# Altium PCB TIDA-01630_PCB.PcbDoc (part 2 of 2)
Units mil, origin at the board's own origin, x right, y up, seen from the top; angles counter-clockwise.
Board outline 3155 x 2050 mil, 4 copper layers (Top Layer, Signal Layer 1, Signal Layer 2, Bottom Layer), stack 49.055 mil thick; 119 components, 66 nets, 330 pads, 436 vias.
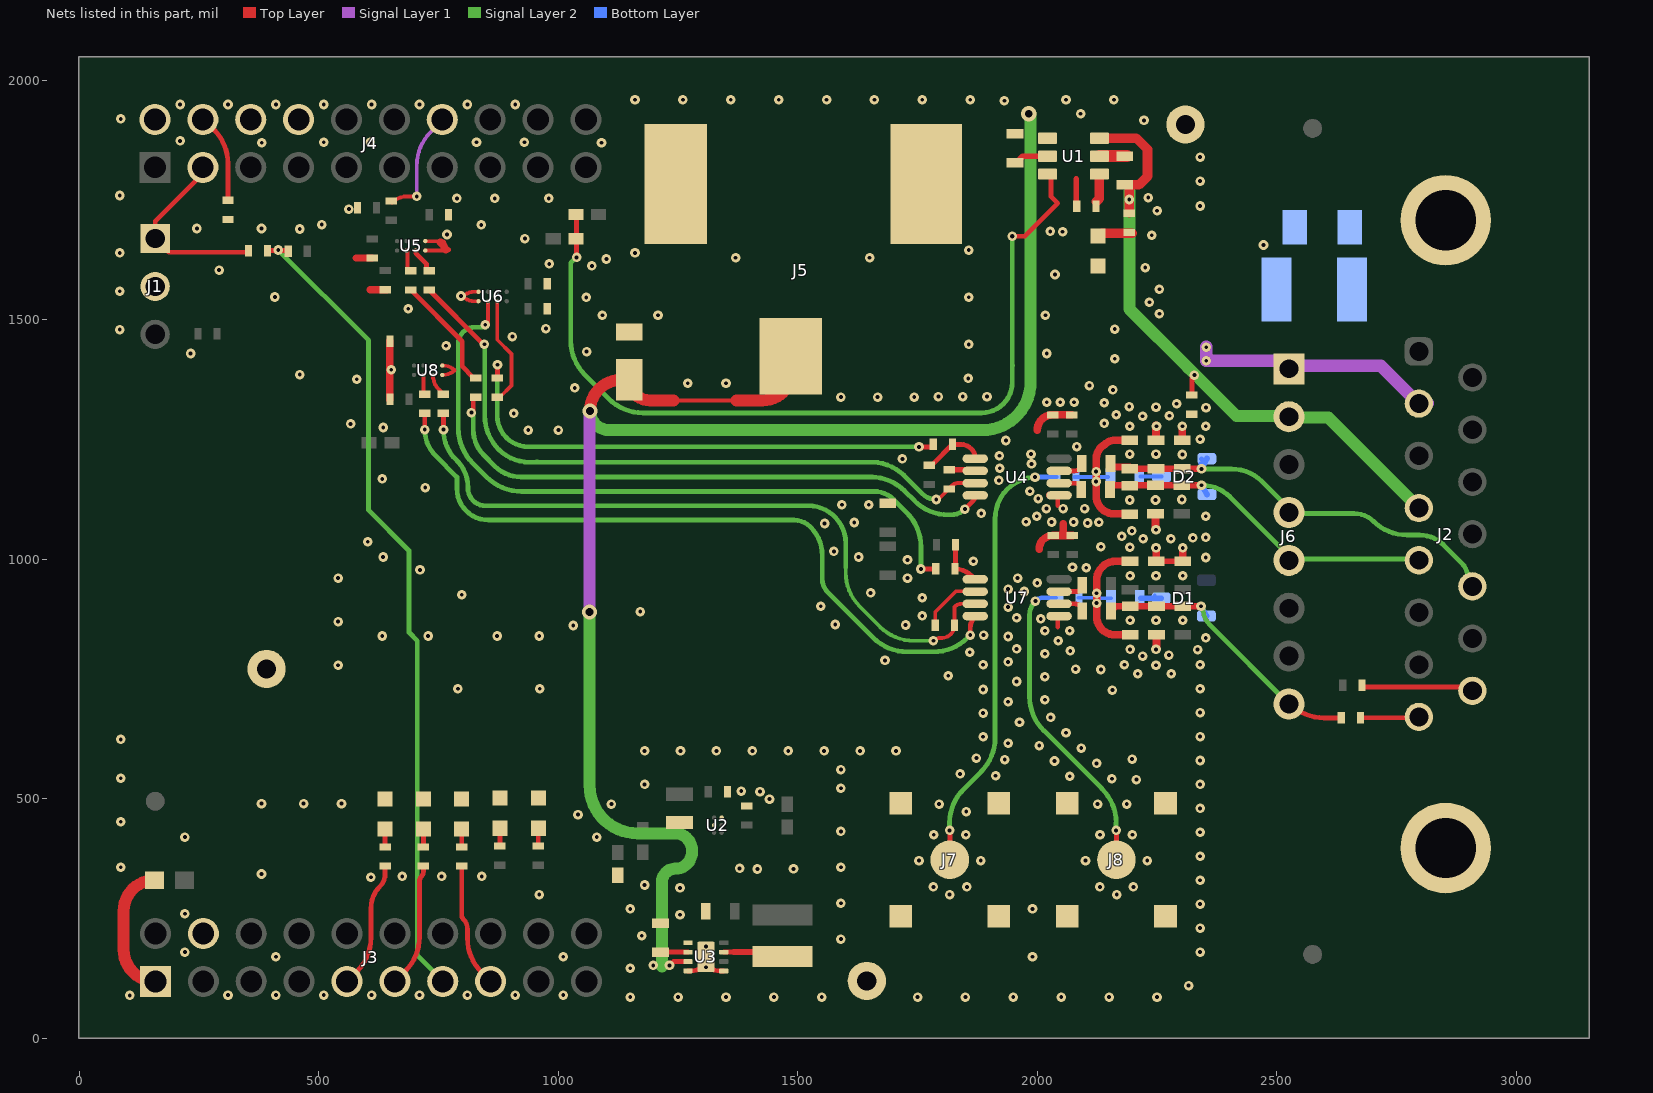
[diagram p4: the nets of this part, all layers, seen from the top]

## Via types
v1: diameter 20, hole 8, Top Layer to Bottom Layer, tented both sides, 371 vias
v2: diameter 20, hole 8, Top Layer to Bottom Layer, 51 vias
v3: diameter 32, hole 16, Top Layer to Bottom Layer, 9 vias
v4: diameter 20, hole 10, Top Layer to Bottom Layer, 3 vias
v5: diameter 19.68, hole 7.87, Top Layer to Bottom Layer, 2 vias

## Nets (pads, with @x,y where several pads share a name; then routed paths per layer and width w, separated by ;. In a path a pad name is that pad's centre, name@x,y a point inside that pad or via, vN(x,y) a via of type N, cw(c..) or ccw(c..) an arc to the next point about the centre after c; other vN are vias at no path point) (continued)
CLK_P: C19.2 D1.2 J6.8 R5.1 R38.1 R39.2 R42.1 | length 600.7
  Top Layer w10: R38.1@2304,902 R38.1@2304,902.33 ; J6.8@2528.09,698.34 ccw(c2598.8,769.05) 2598.8,669.05 R5.1@2634.79,669.05
  Top Layer w14: R39.2@2154,892 2164.33,902.33 R42.1@2194,902.33 C19.2@2249,902.33 R38.1@2304,902.33 ; R38.1@2304,902 v2@2336,902
  Signal Layer 2 w10: v2(2342,902) v2@2345.92,902 ; v2@2345.97,898.03 ccw(c2395.2,898.03) 2360.39,863.23 J6.8@2525.63,697.98
  Bottom Layer w12: v2(2342,902) D1.2@2353.24,881.6
DATA_N: C15.1 D2.1 J2.13 J6.4 R29.1 R31.2 R32.2 | length 911.9
  Top Layer w14: R31.2@2153,1200 2160,1193 R29.1@2193,1193 ; R29.1@2193,1189 C15.1@2248,1189 R32.2@2303,1189 ; R32.2@2307,1189 v2(2343,1189)
  Signal Layer 2 w10: v2(2343,1189) 2405.58,1189 cw(c2405.58,1098.66) 2469.46,1162.54 2518.7,1113.3 ccw(c2540.37,1134.96) J6.4@2540.37,1104.32 ; J6.4@2519.38,1095.95 2661.64,1095.95 cw(c2661.64,1037.76) 2702.78,1078.91 ; J6.4@2528.01,1096.52 J6.4@2529.45,1097.97 ; 2701.43,1080.07 ccw(c2772.15,1150.79) 2772.15,1050.79 2798.43,1050.79 cw(c2798.43,979.84) 2848.6,1030.01 2886.64,991.96 cw(c2856.98,962.3) J2.13@2898.93,962.3 ; J2.13@2901.19,945.89 J2.13@2901.19,969.31
  Bottom Layer w10: D2.1@2343,1209.83 2342.83,1210 D2.1@2343,1210
  Bottom Layer w12: v2(2343,1189) D2.1@2343,1199.51 ; v2@2343.16,1189.5 2347.25,1197.28 D2.1@2354.24,1210.4 D2.1@2354.41,1210.9
DATA_P: C12.2 D2.2 J2.5 J6.5 R22.1 R23.2 R28.2 | length 744.1
  Top Layer w14: R23.2@2152,1149 2158,1155 2193,1155 2215.5,1155 C12.2@2247,1155 R22.1@2302,1155 ; R22.1@2305,1155 v2(2343,1155)
  Signal Layer 2 w10: v2(2343,1155) cw(c2343,1070.46) 2402.78,1130.24 J6.5@2530.33,1002.68 ; J6.5@2525.25,999.52 J6.5@2533.31,999.52 ; J6.5@2530.55,996.76 J6.5@2533.31,999.52 ; J6.5@2535.33,1001.54 J6.5@2534.63,1000.84 ; J2.5@2799.39,1000.84 J6.5@2534.63,1000.84 ; J6.5@2533.31,999.52 J6.5@2534.63,1000.84
  Bottom Layer w10: v2@2341,1151.17 cw(c2341.83,1151.17) 2341.83,1152 2343,1153.17 v2(2343,1155)
  Bottom Layer w12: v2(2343,1155) D2.2@2354.24,1135.6
ENCODERCABLESHIELD: C1.1 J2.16 J2.17 R1.2
GND: C1.2 C2.2 C3.2 C4.1 C5.2 C6.2 C7.2 C8.2 C9.2 C10.2 C11.2 C12.1 C13.1 C14.1 C15.2 C16.2 C17.2 C18.2 C19.1 C20.1 C21.1 C22.2 C23.1 C24.1 C25.2 D1.3 D2.3 D3.1 D4.1 D5.1 D6.2 D7.1 D8.1 D9.1 J1.2 J2.2 J3.4 J4.2 J5.2 J5.3 J6.1 J7.2 J7.3 J7.4 J7.5 J8.2 J8.3 J8.4 J8.5 R1.1 R3.2 R21.1 R32.1 R34.2 R37.1 R46.1 TP1.1 TP2.1 TP3.1 U1.2 U2.A2 U3.1 U3.4 U3.5 U3.9@1308,170 U4.5 U5.D1 U5.D2 U6.D1 U6.D2 U7.5 U8.D1 U8.D2 | length 1763.6
  Top Layer w8: U5.D1@721.82,1644.8 766.73,1644.8 ccw(c766.73,1652.52) 772.19,1647.06 ; U5.D2@721.82,1664.48 756.84,1664.48 cw(c756.84,1658.19) 761.29,1662.64 ; U8.D1@757.53,1385.16 759.24,1385.16 ccw(c759.24,1418.76) 770,1386.93 ccw(c759.24,1418.76) 783,1395 ccw(c759.24,1371.24) 759.24,1404.84 U8.D2@757.53,1404.84 ; U6.D2@833.01,1539.21 824.3,1539.21 cw(c824.3,1572.81) 800.54,1549.05 cw(c824.3,1525.29) 824.3,1558.89 U6.D1@833.01,1558.89
  Top Layer w10: U3.4@1270.6,140.47 1275.34,140.47 ccw(c1275.34,186.66) U3.9@1307,153.03 ; U3.9@1306,154 ccw(c1338.66,186.66) U3.9@1307,153.03 ; U3.5@1345.4,140.47 1338.66,140.47 cw(c1338.66,186.66) U3.9@1307,153.03 ; 2043,859 U7.5@2043,879 ; 2043,1112 U4.5@2043,1133
  Top Layer w12: C2.2@1955.46,1827.74 1969.77,1842.05 U1.2@2021.59,1842.05 ; C4.1@2081.49,1747.35 2081.49,1794.13 ; C22.2@2248.73,996.16 R46.1@2303.73,996.16 R46.1@2311.77,996.16
  Top Layer w15: 577.31,1629.31 C14.1@611.37,1629.31
  Top Layer w16: 607.44,1563.11 C13.1@641.28,1563.11 ; C23.1@648,1334 C24.1@648,1456 ; 753.86,1662.64 cw(c715.24,1624.01) 764.76,1647.06 ; 2000,1269.76 cw(c2032,1269.76) C11.2@2032,1301.76 C10.2@2072,1302 ; 2004,1021 cw(c2033,1021) C17.2@2033,1050 C18.2@2073,1050 C18.2@2074,1050 ; U4.5@2026.39,1133.61 U4.5@2045.6,1133.61 ; U7.5@2028.38,881.62 U7.5@2045.6,881.62 ; 2054,1050 2054,1074 ; C12.1@2247,1092 2247,1065 ccw(c2248,1065) 2248,1064 v1(2248,1062) ; v1(2248,812) ccw(c2248,813) 2249,813 C19.1@2249,842.33 ; v1(2248,1024) cw(c2248,1023.27) 2248.73,1023.27 C22.2@2248.73,996.16 ; C15.2@2248,1249 v1@2248,1280 ; R32.1@2303,1249 v1(2303,1278) ; v1@2303,1279 v1(2303,1278) ; R46.1@2303.73,996.16 2303.73,1024 v1(2304,1024) ; v1@2304,1277 ccw(c2303,1277) v1(2303,1278)
  Signal Layer 1 w26: v1@2353,1444 v1(2353,1443) v1(2353,1415) J6.1@2506.67,1415 ; J6.1@2520.71,1390.38 J6.1@2535.16,1404.84 ; J6.1@2527.1,1404.84 J6.1@2535.16,1404.84 ; J6.1@2537.18,1406.85 J6.1@2535.16,1404.84 ; J2.2@2815.37,1325.95 2795.78,1325.95 2716.89,1404.84 J6.1@2535.16,1404.84
  Bottom Layer w8: C16.2@2215.13,1173 D2.3@2259.76,1173
  Bottom Layer w12: C25.2@2216.27,919 D1.3@2258.76,919
  other v1: 1150,86 1250,86 1350,86 1450,86 1550,86 1750,86 1850,86 1950,86 2050,86 2150,86 2250,86 104.73,89.5 310,90 410,90 510,90 610,90 710,90 810,90 910,90 1010,90 2316,110 1150,146 410,170 1010,170 1990,170 220,180 2340,180 1590,207 1174,214 2340,230 1254,258 220,260 1150,270 1990,270 2340,280 1590,282 960,300 1816.99,300.01 2165.99,300.01 1254,314 1783,316 1853,316 2130.76,316 2200.76,316 1180,320 2340,330 608.3,336.37 674,338 756,338 840,338 380,343 1415.45,353.43 1491.04,353.73 1378.52,354.66 86,357 1590,357 1753,371 1882,371 2100.76,371 2229.76,371 2340,380 220,420 1080,420 1784,425 1851,425 2131,425 2198.76,425 2340,430 1590,432 86,452 1041,467 1851.82,473.36 2340,480 1110.55,488.96 1795,489 2125.99,489.01 2187,489 380,490 468,490 547,490 1440.81,499.29 1421,515 1382,516 1590,522 1180,530 2340,530 2207,540 2155.99,542.01 86,543 2068,547 1913,548 1839,552 1590,561 2124,574 2036,579 2340,580 1932,582 2198,583 1873,585 1180,600 1255,600 1330,600 1405,600 1480,600 1555,600 1630,600 1705,600 2092,606 2004,611 1939,616.17 86,624 1887,629.75 2340,630 2060,638 1963,660 2028.01,669.99 1887,679 2340,680 1939,702.58 2016,707 2157,727 1887,728.25 790,730 961,730 2340,730 1957,745 2016,755 1814,757 2210,761 2280,761 2133,770 2080,771 540,779 2248,779 1887,780 2182,780 2340,780 1939,786 1682,789 2220,798 2275,800 2016,803 1859,806 2069,809 2194,812 2334.81,811.52 1957,813 2044,830 2352,836 1939,839 632,840 728,840 872,840 960,840 1888,842 2016,851 2068,851 1031,862 1725,863 1578,864 540,870 2194,873 2248,873 2304,873 2007.46,875.61 1957,878 1760,882 1171,891 1939,900.32 1548,902 1760,920 798,926 1652,930 1973,933 1939,938 2000,951 540,961 1729,961 1959,961 2194,966 2248,966 2304,966 711,978 2102.32,982.46 2073.56,983.75 1866.57,995.98 1729,999 2352,1004 634,1005 1627,1005 1575.38,1016.57 2193.42,1025.29 2132.9,1026.55 602,1037 2221,1043 2279,1043 2325,1045 2352,1046 2176.46,1048.07 2197.65,1059.37 1556.01,1074.91 2105.18,1076.01 1618,1077 2128.64,1077.45 1976.59,1078.44 2030,1078 2076,1078 1999,1090 2352,1090 1883,1096 2019,1106 2054,1106 2099,1106 1592,1114 1648,1114 2193,1124 2247,1124 2302,1125 2002,1127 1984.75,1142.41 722,1150 1920,1165 632,1168 1921.77,1190.34 1987.96,1199.39 1718.33,1209.92 1920.92,1216.38 2303,1219 1987,1220 2193,1220 2248,1220 2082.47,1235.64 1934.58,1248.25 2340,1251 937,1270 1000,1270 634.13,1275.45 2193,1278 2249,1278 2352,1278 566,1283 2140,1284 2220,1299 2276,1300 2165,1302 906.61,1304.82 2352.47,1316.98 2248,1318 2192,1319 2291,1325 2140,1327 2020,1328 2048,1328 2077,1328 1590,1339 1666.5,1339 1743,1339 1793.67,1340 1844.33,1340 1895,1340 2158,1354 1034,1358 2109,1363 1270,1368 1350,1368 578.83,1376.18 1856,1378 460,1386 651,1396 2162,1419 232,1430 2020,1430 1059,1434 765.48,1446.19 1857,1449 903.84,1465.32 84,1480 2162,1481 974,1482 1092,1510 1208,1510 2017,1510 2255,1513 686.3,1523.34 2234.12,1537.01 1058,1547 408,1548 1857,1547.5 796.54,1550.05 84,1560 2255,1564 2037,1595 291.44,1604.07 2225.57,1609.26 1069.89,1612.92 980.9,1617.08 1100.26,1627.34 1370,1630 1650,1630 84,1640 1160,1640 1857,1646 2472.43,1656.49 930,1670 2239,1677 767.38,1678.47 2053,1684.29 2027,1685 460,1690 245,1691 380,1691 838.7,1698.42 505.62,1699.11 2250.29,1728.25 562.43,1731.48 2340,1738 788,1754 867,1754 980,1754 2231.71,1755.58 84,1760 2340,1790 2340,1840 380.4,1870.08 1090,1870 510,1871 607.1,1870.74 829,1871 929,1871 210,1874 2222.94,1916.76 86,1920 2090.6,1930.69 210,1950 310,1950 410,1950 510,1950 610,1950 710,1950 810,1950 910,1950 1931.42,1957.84 1160,1960 1260,1960 1360,1960 1460,1960 1560,1960 1660,1960 1760,1960 1860,1960 2060,1960 2160,1960
  other v5: 1308,148.35 1308,191.65
GPIO52: J3.15 R9.2 | length 259.9
  Top Layer w10: R9.2@798,359.57 798,257.66 ccw(c811.66,257.66) 802,248 cw(c782.69,228.69) 810,228.69 810,208.53 ccw(c910,208.53) 839.29,137.82 J3.15@858.49,118.62
GPIO94: J3.11 R10.2 | length 260.1
  Top Layer w10: J3.11@658.49,118.62 680.71,140.84 ccw(c610,211.55) 710,211.55 710,328.34 cw(c723.66,328.34) 714,338 ccw(c704.34,347.66) 718,347.66 R10.2@718,359.57
GPIO97: J3.9 R11.2 | length 265.2
  Top Layer w10: J3.9@558.49,118.62 579.21,139.34 ccw(c508.5,210.05) 608.5,210.05 608.5,270.93 cw(c675.07,270.93) 628,318 ccw(c603.86,342.14) 638,342.14 R11.2@638,359.57
GPIO130: J4.8
GPIO131: J4.6
NetC4_2: C4.2 U1.4 | length 59.8
  Top Layer w20: C4.2@2123.77,1747.35 2129.86,1753.44 U1.4@2129.86,1804.65
NetC16_1: C16.1 R28.1 R29.2 R33.2 | length 362.3
  Top Layer w16: v2@2123,1183 v2(2123,1162.73) 2123,1132.95 ccw(c2160.95,1132.95) 2160.95,1095 R28.1@2193,1095 ; v2(2123,1183.27) 2123,1209.84 ; 2123.13,1209.84 cw(c2157.45,1209.84) 2138.41,1238.4 ; 2140.94,1239.93 ccw(c2157.45,1209.84) 2138.45,1238.43 2141.41,1240.4 ; 2141,1240 cw(c2162.73,1218.27) 2141.41,1240.4 ; R29.2@2193,1249 2162.73,1249 ccw(c2162.73,1218.27) 2150.5,1246.46 ; 2141.41,1240.4 cw(c2162.73,1218.27) 2150.5,1246.46 ; 2141.41,1240.4 2150.5,1246.46
  Bottom Layer w8: R33.2@2078.12,1172 v2@2121,1172 ; v2@2123,1172 C16.1@2148,1172
  Bottom Layer w16: v2(2123,1162.73) 2123,1172 v2(2123,1183.27)
NetC25_1: C25.1 R42.2 R43.1 R47.2 | length 347.6
  Top Layer w16: R43.1@2193.73,996.16 2164.01,996.16 ccw(c2164.01,956.15) 2124,956.15 2124,927.32 2124,881.2 ccw(c2162.87,881.2) 2162.87,842.33 R42.2@2194,842.33
  Bottom Layer w8: R47.2@2085.62,920 v2@2123,920 ; 2124,919 C25.1@2154,919
  Bottom Layer w16: v2(2124,908.73) 2124,919 v2(2124,929.27)
NetD3_2: D3.2 R9.1 | length 37.3
  Top Layer w10: R9.1@798,399.57 D3.2@798,436.87
NetD4_2: D4.2 R10.1 | length 37.3
  Top Layer w10: R10.1@718,399.57 D4.2@718,436.87
NetD5_2: D5.2 R11.1 | length 37.3
  Top Layer w10: R11.1@638,399.57 D5.2@638,436.87
NetD7_2: D7.2 R15.2 | length 64.5
  Top Layer w20: D7.2@2134.27,1681.46 R15.2@2198.8,1681.46
NetD8_2: D8.2 R17.1 | length 37.3
  Top Layer w10: R17.1@878,401.2 D8.2@878,438.5
NetD9_2: D9.2 R20.1 | length 37.3
  Top Layer w10: R20.1@958,401.2 D9.2@958,438.5
NetJ1_1: J1.1 J4.3 R8.2 | length 397.3
  Top Layer w10: J4.3@261.01,1817.45 261.01,1809.64 158,1706.63 J1.1@158,1670 186.57,1641.43 R8.2@353.34,1641.43
NetJ2_8: J2.8 R5.2 | length 147
  Top Layer w10: R5.2@2674.13,669.48 J2.8@2821.14,669.48
NetJ2_15: J2.15 R4.1 | length 249
  Top Layer w10: R4.1@2680.06,733.49 J2.15@2929.1,733.49
NetJ3_1: J3.1 R2.2 | length 286.2
  Top Layer w25: R2.2@156.5,330 ccw(c156.5,265.5) 92,265.5 92,185.11 ccw(c158.49,185.11) J3.1@158.49,118.62
NetJ3_13: J3.13 R7.2 R8.1 | length 1710.4
  Top Layer w10: R8.1@395.26,1645.47 395.73,1645 R7.2@435.72,1645
  Signal Layer 2 w10: v1(414.83,1646.08) 603.69,1457.21 603.69,1102.6 688,1018.29 688,847.47 705.43,830.04 705.43,173 J3.13@759.35,119.09
NetJ4_4: J4.4 R3.1 | length 188.6
  Top Layer w10: J4.4@258.52,1919.62 280.71,1897.43 cw(c210,1826.72) 310,1826.72 R3.1@310,1750 R3.1@310,1748
NetJ4_14: J4.14 R6.1 | length 227.9
  Top Layer w8: R6.1@652.51,1745.13 cw(c683.8,1713.83) 683.8,1758.09 v1(704.24,1758.09)
  Signal Layer 1 w8: v1(704.24,1758.09) 704.24,1822.07 cw(c804.24,1822.07) 733.53,1892.78 J4.14@754.85,1914.1
NetJ7_1: J7.1 R33.1 | length 920.9
  Top Layer w10: v2(1817,434) 1817.59,434 J7.1@1817.59,372.51
  Signal Layer 2 w10: v2(1817,434) 1817,449.58 cw(c1917,449.58) 1846.29,520.29 1882.71,556.71 ccw(c1812,627.42) 1912,627.42 1912,1085 cw(c1999,1085) v2@1999,1172
  Bottom Layer w10: v2@1999,1172 R33.1@2039.38,1172
  other v2: 1995.29,1171.89
NetJ8_1: J8.1 R47.1 | length 656.4
  Top Layer w10: v2(2164.76,434) 2165.34,434 J8.1@2165.34,372.51
  Signal Layer 2 w10: v2(1996,913) ccw(c2024.97,884.03) 1984,884.03 1984,713.42 ccw(c2084,713.42) 2013.29,642.71 2135.47,520.53 cw(c2064.76,449.82) 2164.76,449.82 v2(2164.76,434) ccw(c2163.34,435.41) v2@2165.34,435.41
  Bottom Layer w10: v2(1996,913) cw(c2012.9,896.1) 2012.9,920 2038.38,920
NetL1_2: L1.2 U2.B1
NetL2_1: L2.1 U3.7 | length 83.7
  Top Layer w10: U3.7@1345.4,179.84 1366,179.84 1366,180 ; L2.1@1458.46,179.84 cw(c1458.46,170.3) L2.1@1468,170.3
  Top Layer w12: 1366,180 L2.1@1414,180
NetR12_1: R12.1 R13.2 U1.3 | length 1795.8
  Top Layer w10: R13.2@1037.45,1720.99 1038.07,1720.37 v1(1038.07,1630.62) ; v4(1948,1674.84) 1974.13,1674.84 2042.94,1743.65 ; U1.3@2028.52,1800.21 2028.52,1758.07 2042.92,1743.67
  Signal Layer 2 w10: v1@1036.49,1629.52 1026,1619.03 1026,1456.22 ccw(c1126,1456.22) 1055.29,1385.51 1105.51,1335.29 ccw(c1176.22,1406) 1176.22,1306 1884,1306 ccw(c1884,1370) 1948,1370 1948,1405.2 ; v4(1948,1674.84) 1948,1405.2 ; 1948.19,1405.02 1948,1405.2
NetR14_1: R14.1 U1.5 | length 57.3
  Top Layer w25: U1.5@2129.86,1842.05 R14.1@2187.13,1842.05
NetR23_1: R23.1 U4.6 | length 53.9
  Top Layer w10: U4.6@2045.6,1159.2 2078.8,1159.2 cw(c2078.8,1146) R23.1@2092,1146
NetR24_1: R24.1 R25.2 U4.1 | length 122.8
  Top Layer w10: R24.1@1782.01,1199.61 1782.61,1199.61 R25.2@1823,1240 1841,1240 cw(c1841,1210) U4.1@1871,1210
NetR25_1: R25.1 R26.2 | length 1080.7
  Top Layer w10: R26.2@872.71,1378.65 v1@872.71,1404.37 ; v2(1753,1235) R25.1@1783.28,1235
  Signal Layer 2 w10: 872.12,1300.38 v1@872.12,1407.59 ; 872.38,1299.99 ccw(c937.03,1299.99) 937.03,1235.34 953.6,1235.34 v2(1753,1235)
  other v1: 872.85,1406.63
NetR26_1: R26.1 U6.B2 | length 228.9
  Top Layer w8: U6.B2@872.38,1539.21 872.38,1458.73 902.2,1428.91 902.2,1389.12 ; R26.1@872.71,1338.65 877.39,1338.65 902.11,1363.37 902.11,1365.78 ; 902.34,1364.67 902.34,1389.12
NetR27_1: R27.1 R36.1 U4.3 | length 1433.5
  Top Layer w8: v2(1789,1125) ccw(c1789,1135.34) 1796.31,1128.03 1823.27,1154.99 ; 1823.28,1155 cw(c1833.43,1144.86) 1833.43,1159.2 U4.3@1870.4,1159.2
  Top Layer w10: R36.1@729.78,1562.7 729.89,1562.59 v2@845.21,1447.27
  Signal Layer 2 w10: v2@846.29,1441.89 846.29,1300.03 ccw(c946.29,1300.03) 875.58,1229.32 ccw(c938.95,1292.69) 938.95,1203.07 956.87,1203.07 ; 953.88,1203.26 956.87,1203.26 1657.21,1202.96 ; 1654.4,1203 cw(c1654.4,1107.4) 1657.21,1202.96 ; 1659.87,1202.96 1657.21,1202.96 ; v2(1789,1125) cw(c1789,1166.04) 1759.98,1137.02 1722,1175 ccw(c1654.4,1107.4) 1657.21,1202.96
  other v2: 845.57,1449.26
NetR27_2: R27.2 U4.2 | length 31.1
  Top Layer w12: R27.2@1825.28,1187.31 U4.2@1856.42,1187.31
NetR30_1: R30.1 R35.1 | length 238
  Top Layer w10: R35.1@691.17,1562.87 799.01,1455.03 799.01,1402.93 R30.1@822.61,1379.33
NetR30_2: R30.2 U4.4 | length 1208.2
  Top Layer w10: v2(818.37,1306.66) 822.08,1310.38 R30.2@822.08,1337.69 ; v2(1849,1105) 1865.3,1121.3 ccw(c1852.99,1133.61) U4.4@1870.4,1133.61
  Signal Layer 2 w10: v2@822,1303.03 822,1272 ccw(c899.25,1272) 844.63,1217.37 867.37,1194.63 ccw(c922,1249.25) 922,1172 ; 926.09,1171.99 1653.73,1171.99 ; 1652.58,1172 cw(c1652.58,1072) 1653.73,1171.99 ; 1656.67,1171.99 1653.73,1171.99 ; v2(1849,1105) cw(c1820.03,1133.97) 1820.03,1093 1814.42,1093 cw(c1814.42,1193) 1743.71,1122.29 1723.29,1142.71 ccw(c1652.58,1072) 1653.73,1171.99
NetR31_1: R31.1 U4.7 | length 56.1
  Top Layer w10: U4.7@2045.6,1184.79 2077.79,1184.79 ccw(c2077.79,1200) R31.1@2093,1200
NetR35_2: R35.2 U5.B1 | length 42
  Top Layer w8: U5.B1@682.65,1645.02 684.66,1643 R35.2@684.66,1603.88
NetR36_2: R36.2 U5.C1 | length 46
  Top Layer w10: U5.C1@702.33,1645.02 702.33,1639.26 724.78,1616.81 R36.2@724.78,1608.29
NetR39_1: R39.1 U7.6 | length 57.1
  Top Layer w10: U7.6@2045.6,907.21 2078.79,907.21 cw(c2078.79,892) R39.1@2094,892
NetR40_1: R40.1 R41.2 U7.1 | length 102.3
  Top Layer w10: R41.2@1827.01,977.29 1829.43,979.71 R41.2@1829.43,979.98 ; R40.1@1829.43,1030.82 R41.2@1829.43,979.98 ; U7.1@1870.4,958.39 1863.49,965.3 ccw(c1828,929.81) R41.2@1829.43,979.98
NetR41_1: R41.1 U6.C2 | length 1492.6
  Top Layer w8: v2@852.02,1488.7 852.7,1489.38 852.7,1520.14 ; 852.7,1512.07 U6.C2@852.7,1539.21
  Top Layer w10: v2(1757,980) R41.1@1788,980
  Signal Layer 2 w10: v2@848.73,1484.6 824.52,1484.6 ccw(c824.52,1451.08) 791,1451.08 791,1274.08 ccw(c895,1274.08) 821.46,1200.54 835.43,1186.57 849.54,1172.46 ccw(c923.08,1246) 923.08,1142 1658.96,1142 cw(c1658.96,1083.96) 1700,1125 1727.71,1097.29 cw(c1657,1026.58) 1757,1026.58 v2(1757,980)
  other v2: 847.39,1489.93
NetR44_1: R44.1 R51.1 U7.3 | length 1488.1
  Top Layer w8: v2(1783,830) cw(c1797.49,815.51) 1797.49,836 1801,836 ccw(c1801,862) R44.1@1827,862 1827,901 cw(c1841.98,886.02) 1841.98,907.21 U7.3@1870.4,907.21
  Top Layer w10: v2(760,1271) R51.1@760,1305
  Signal Layer 2 w8: 1600,983 1600,972.42 ccw(c1700,972.42) 1611.16,926.51 ccw(c1700,972.42) 1629.29,901.71 1671.71,859.29 ccw(c1742.42,930) 1742.42,830 v2(1783,830)
  Signal Layer 2 w10: v2(760,1271) ccw(c849.33,1271) 781.3,1213.11 786.67,1207.74 cw(c727.93,1149) 791.35,1202.65 ; 791.73,1202.78 cw(c728.31,1149.14) 811.38,1149.14 ; 811,1149 ccw(c848,1149) 848,1112 1521.85,1112 cw(c1521.85,1033.85) 1600,1033.85 1600,983
NetR44_2: R44.2 U7.2 | length 117.2
  Top Layer w8: R44.2@1787,862 1787,890.27 1830.32,933.59 U7.2@1858.02,933.59
NetR45_1: R45.1 U7.7 | length 55.9
  Top Layer w10: U7.7@2045.6,932.8 2080.8,932.8 ccw(c2080.8,946) R45.1@2094,946
NetR50_1: R50.1 U7.4 | length 1505.4
  Top Layer w10: v2(721,1271) R50.1@721,1305 ; v2(1860,842) 1860,856.5 cw(c1895.51,856.5) U7.4@1870.4,881.62
  Signal Layer 2 w10: v2(721,1271) ccw(c798.25,1271) 743.63,1216.37 788,1172 788,1148 ccw(c854,1148) 854,1082 1492.2,1082 cw(c1492.2,1034.2) 1526,1068 1526.32,1067.68 ; 1526.7,1067.34 cw(c1467.55,1008.18) 1551.21,1008.18 1551.21,958.62 ccw(c1590.12,958.62) 1562.6,931.1 1571.78,921.92 ; 1571.04,922.96 1657.71,836.29 ccw(c1728.42,907) 1728.42,807 1783.58,807 ccw(c1783.58,907) 1854.29,836.29 v2(1860,842)
NetR50_2: R50.2 U8.B1 | length 40.9
  Top Layer w8: U8.B1@718.16,1385.16 718.16,1351.86 ccw(c727.86,1351.86) R50.2@721,1345
NetR51_2: R51.2 U8.C1 | length 47.5
  Top Layer w8: U8.C1@737.84,1385.16 ccw(c781.3,1385.16) 750.57,1354.43 R51.2@760,1345
VIN: C2.1 C5.1 D6.1 J5.1 U1.1 U3.2 U3.3 | length 3519.7
  Top Layer w8: 1240,1332 1372,1332
  Top Layer w10: C5.1@1213,180 1270.6,180 U3.2@1270.6,179.84 ; 1240,160 1240.16,160.16 U3.3@1270.6,160.16
  Top Layer w25: v3(1066,1310) cw(c1130.8,1310) 1130.8,1374.8 D6.1@1148,1374.8 ccw(c1190.8,1374.8) 1190.8,1332 1240,1332 ; 1372,1332 1426.06,1332 ccw(c1426.06,1394.02) J5.1@1488.08,1394.02
  Signal Layer 1 w25: v3(1065,890) 1065,1309 v3(1066,1310)
  Signal Layer 2 w25: v3(1065,890) 1065,528 ccw(c1165,528) 1165,428 1243.03,428 cw(c1243.03,392) 1279.03,392 1279.03,389.03 cw(c1244,389.03) 1244,354 ccw(c1244,326) 1216,326 1216,150 ; v3(1066,1310) ccw(c1106,1310) 1106,1270 1886,1270 ccw(c1886,1370) 1986,1370 v3@1986,1930.4
  other v2: 1198,152 1232,152
  other v3: 1981.96,1930.36
VSUPPLY_ENC: C3.1 J2.4 J6.2 R14.2 R15.1 U1.6 | length 1338.2
  Top Layer w10: C3.1@2323,1343 v1@2323,1379.69
  Top Layer w20: U1.6@2129.86,1879.45 2207.06,1879.45 2230.07,1856.44 ; R15.1@2192.52,1723.47 2192.52,1782.11 2212.37,1782.11 2230.3,1800.04 2230.3,1855.97
  Signal Layer 2 w25: 2192.56,1768.44 2192.56,1522.51 2314.95,1400.11 2315.67,1400.11 2415.92,1299.86 J6.2@2524.72,1299.86 ; J6.2@2515.56,1295.97 2608.2,1295.97 2795.1,1109.07 J2.4@2798.43,1105.74
  other v1: 2328.13,1384.81
  other v2: 2192.23,1751.61
pads on no net: FID1.1 FID2.1 FID3.1 FID4.1 FID5.1 FID6.1 J2.1 J2.3 J2.6 J2.7 J2.9 J2.10 J2.11 J2.12 J2.14 J3.2 J3.3 J3.5 J3.6 J3.7 J3.8 J3.10 J3.12 J3.14 J3.16 J3.18 J3.19 J3.20 J4.5 J4.9 J4.10 J4.11 J4.13 J4.15 J4.16 J4.17 J4.19 J6.3 J6.6 LBL1.0 U3.8 U3.9@1308,152.28 U3.9@1308,187.72
copper on no net:
  other v1: 550.26,1636.96

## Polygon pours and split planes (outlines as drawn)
GND on Bottom Layer "BOT GND" (solid, remove dead copper, pour order 40): 67.4,1923.4 113,1969 2314,1969 2401.88,1969 2569.59,1801.29 2569.59,331.59 2306,68 111.18,68 66.4,112.78
ENCODERCABLESHIELD on Bottom Layer "BOTTOM_LAYER_ENCODERCABLESHIELD_P028" (solid, remove dead copper, pour order 28): 2718.38,273.07 3038.87,273.07 cw(c3038.87,271.58) 3039.93,272.63 3039.93,1828.11 2736.49,1828.11 ccw(c2716.91,1712.18) 2629.63,1790.94 2629.63,300.04 ccw(c2697.93,373.08) 2697.93,273.07
GND on Signal Layer 1 "SIG1 GND" (solid, remove dead copper, pour order 42): 68,1925 112,1969 2313,1969 2402.52,1969 2569.65,1801.87 2569.65,332.65 2305,68 111.06,68 67,112.07
ENCODERCABLESHIELD on Signal Layer 1 "SIGNAL_LAYER_1_ENCODERCABLESHIELD_P034" (solid, remove dead copper, pour order 34): 2718.42,272.85 3038.91,272.85 cw(c3038.91,271.38) 3039.97,272.41 3039.97,1827.97 2718.42,1827.97 ccw(c2713.83,1714.5) 2625.87,1786.32 2625.87,303.62 ccw(c2698.09,373) 2698.09,272.85
GND on Top Layer "TOP GND" (solid, remove dead copper, pour order 36): 68.02,1924.02 113,1969 2314,1969 2402.52,1969 2569.59,1801.94 2569.59,331.59 2306,68 111.5,68 67.02,112.48
VIN on Top Layer "u2 vIN" (solid, remove dead copper, pour order 26): 1961.37,1948.51 1929.97,1917.11 1929.97,1899.44 1929.97,1877.35 1937.45,1869.87 1939.83,1867.49 2033.61,1867.49 2043.47,1867.49 2047.2,1871.23 2044.49,1873.95 2044.49,1902.15 2044.49,1916.43 2012.4,1948.51
GND on Signal Layer 2 "SIG2 GND" (solid, remove dead copper, pour order 38): 69,1925 113,1969 2314,1969 2403.81,1969 2569.59,1803.22 2569.59,331.59 2306,68 111.06,68 68,111.07

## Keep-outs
Keep-Out Layer:
  text ".Layer_Name" at 577,-858.49 h60

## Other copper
Top Layer:
  pour cut-out: 1342,153 1325,170 1325,215.99 1308,233 1308,287 1345,324 1504,324 1538,290 1538,153
  pour cut-out: 1222,428 1222,532 1284,532 1284,428
  region net NetL1_2: 1259.96,464.2 1291.96,464.2 1310.08,452.33 1322.13,450.12 1328.11,448.15 1328.11,441.99 1322.13,440.28 1308.96,436.5 1259.96,436.5
  region net 3V3: 1251.87,496 1296,496 1322.17,457.8 1328.08,457.8 1329.06,463.7 1328,496 1328,528 1251.87,528
  region net GND: 1340,531 1340,498 1337.92,463.7 1337.92,457.8 1343.83,457.8 1355.64,470.59 1451,470.59 1451,521 1447,525 1441,531
  region net 5VUNFILTERED: 1337.92,447.95 1381.24,456 1415,456 1415,430 1366,430 1343.83,440.08 1337.92,442.05
  pour cut-out: 1332,540 1332,451 1467,451 1467,540
  region net VIN: 1188,186 cw(c1200,186) 1200,198 1238,198 cw(c1238,190) 1246,190 1246,150 cw(c1230,150) 1230,134 1204,134 cw(c1204,150) 1188,150
  region net GND: 1326,270 ccw(c1306,270) 1306,290 1208,290 ccw(c1206,258) 1174,260 1174,253.16 ccw(c1196.55,251.69) 1195.08,229.14 1236,229.14 cw(c1236.43,205.57) 1260,206 1260,198 ccw(c1264,198) 1264,194 1282,194 cw(c1282,186) 1290,186 1326,186
  region net 5V: 1658,1022 1720,1022 ccw(c1720,1040) 1738,1040 1738,1048 ccw(c1722,1048) 1722,1064 1658,1064 ccw(c1654.67,1043)
  region net 3V3: 1359.63,246.32 1379.68,246.32 cw(c1379.68,240) 1386,240 ccw(c1390,240) 1390,236 1480,236 ccw(c1485,282.3) 1531.3,277.3 1529.82,294.95 ccw(c1482.69,286.87) 1474.61,334 1370,334 ccw(c1370,314) 1350,314 1350,255.95 ccw(c1359.63,255.95)
  pour cut-out: 1259.11,147.76 1259.11,124.23 ccw(c1279.23,124.23) 1265,110 1340.86,110 ccw(c1340.86,144.14) 1365,120 ccw(c1360.12,124.88) 1367.02,124.88 1367.02,143.02 ccw(c1362.25,143.02) 1365.63,146.4 1363.04,148.98
  text ".Layer_Name" at 577,-858.49 h60
Signal Layer 1:
  pour cut-out: 1222,428 1222,532 1284,532 1284,501 1331,454 1331,428 1284,428
  pour cut-out: 1397.01,140.25 1364.75,140.25 1332,173 1332,243 1377,288 1538.99,288 1538.99,140.25
  region net 5V: 1634,1036 ccw(c1652,1036) 1652,1018 1728,1018 ccw(c1728,1032) 1742,1032 1742,1074 ccw(c1726,1074) 1726,1090 1672,1090 ccw(c1672,1052) 1634,1052
  text ".Layer_Name" at 577,-858.49 h60
Signal Layer 2:
  pour cut-out: 1222,428 1222,532 1284,532 1284,428
  pour cut-out: 1397.01,140.25 1397.01,288 1538.99,288 1538.99,140.25
  region net VIN: 1188,186 cw(c1200,186) 1200,198 1238,198 cw(c1238,190) 1246,190 1246,150 cw(c1230,150) 1230,134 1204,134 cw(c1204,150) 1188,150
  text ".Layer_Name" at 577,-858.49 h60
Bottom Layer:
  region net GND: 2243,905 2273,905 ccw(c2273,913) 2281,913 2281,925 ccw(c2273,925) 2273,933 2243,933 ccw(c2243,927) 2237,927 2237,911 ccw(c2243,911)
  region net GND: 2244,1159 2274,1159 ccw(c2274,1167) 2282,1167 2282,1179 ccw(c2274,1179) 2274,1187 2244,1187 ccw(c2244,1181) 2238,1181 2238,1165 ccw(c2244,1165)
  text ".Layer_Name" at 577,-858.49 h60

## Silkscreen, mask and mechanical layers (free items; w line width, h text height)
Top Overlay:
  circle w14: c1266,1582 r10.44
  region: 550,690 250,690 250,590 550,590
  lines w5: 638,1423 656,1423 ccw(c656,1436) 669,1436 ; 695.84,1547.46 702.34,1540.96 743.8,1540.96 ; 731.29,1577.82 cw(c767.5,1541.61) 767.5,1592.82 ; 902.54,1475.05 902.54,1514.05 ; 902.64,1476.32 ccw(c919.64,1476.32) 919.64,1459.32 ; 1068.52,1638.48 cw(c1068.52,1621.48) 1085.52,1621.48 ; 1397,500 1407,534 1417,534 1421,538 ; 1698.77,1254.69 1763.77,1254.69 ; 2079.61,1678.67 2079.61,1717.67
  lines w8: 2750.9,1860.85 2774.9,1884.85 ; 2773.9,1859.85 2797.9,1883.85 2797.9,1912.85 ; 2797.9,1858.85 2823.9,1884.85
  lines w10: 1202,1582 1266,1582 ; 1232.63,1600.2 cw(c1266,1582) 1235,1560
  lines w12: 2774.9,1884.85 2823.9,1884.85
  lines w20: 94,116 96,116 ; 96,1802 98,1802 ; 1854,1014 1856,1014 ; 1854,1266 1856,1266
  text "*" at 382.96,1719.32 h28
  text "*" at 569.64,1639.3 h28
  text "+" at 1177,1583 h28
  text "-" at 1292,1515 h28
  text "ENC / PWR" at 2025.12,1439.22 h40
  text "z" at 2037.84,1414.64 h26
  text "ENC PWR /  IN 5V" at 1826,1341 h32 r90
  text "z" at 2120,1228 h26
  text "ERR" at 658,570 h42 r90
  text "MODE" at 738,570 h42 r90
  text "ACT" at 818,570 h42 r90
  text "+3.3V" at 898,570 h42 r90
  text "+5V" at 978,570 h42 r90
  text "+3.3V" at 1512,474 h22
  text "+5V" at 1512,434 h22
  text "DATA" at 1742,163 h42
  text "CLOCK" at 2074,163 h42
  text "CM NOISE INJ" at 1797,109 h36
  text ".Layer_Name" at 577,-858.49 h60
Bottom Overlay:
  text ".Layer_Name" at 577,-858.49 h60
Top Paste:
  text ".Layer_Name" at 577,-858.49 h60
Bottom Paste:
  text ".Layer_Name" at 577,-858.49 h60
Top Solder:
  text ".Layer_Name" at 577,-858.49 h60
  text ".Layer_Name" at 577,-858.49 h60
Bottom Solder:
  text ".Layer_Name" at 577,-858.49 h60
Drill Guide:
  text ".Layer_Name" at 577,-858.49 h60
M1 Board Outline:
  lines w10: 0,0 3152.64,0 3152.64,2049 0,2049 0,0
  text ".Layer_Name" at 577,-858.49 h60
M2 Board Dimensions:
  rectangle: 125,-400 500,-275
  rectangle: 0,-275 125,-150
  lines w7: 0,-275 1000,-275 ; 125,-400 125,-150 ; 250,-400 250,-150 ; 500,-400 500,-150 ; 750,-400 750,-150 ; 0,-400 0,-150 1000,-150 1000,-400 0,-400
  text ".Layer_Name" at 577,-858.49 h60
M3 3D STEP Top:
  text ".Layer_Name" at 577,-858.49 h60
M4 3D STEP Bottom:
  text ".Layer_Name" at 577,-858.49 h60
M5 Assembly Top:
  lines w3.94: 6733.83,4017.3 6787.61,3963.52
  lines w10: -292,-930.17 6308,-930.17 ; -292,-726.83 6310,-726.83 ; -292,-523.5 -292,-1133.5 3713,-1133.5 6310,-1133.5 6310,-523.5 -291.5,-523.5 -291.5,-1133.5 1284,-1133.5 ; 2173,-1133.5 2173,-523.5 ; 3440,-726.83 3440,-523.5 ; 4280,-726.83 4280,-523.5 ; 4902,-1140 4902,-937.17
  text "COMPONENTS MARKED 'DNP' SHOULD NOT BE POPULATED." at 1153.5,-318.5 h60
  text "ASSEMBLY VARIANT:" at 1153,-434 h60
  text ".VariantName" at 2189,-434 h60
  text "PCB VIEWED FROM TOP SIDE" at -228.5,-655.67 h60
  text "BOARD #:" at 2248,-655.67 h60
  text ".PRJ_Number" at 2793.5,-655.67 h60
  text "REV:" at 3638,-655.67 h60
  text ".PCB_Rev" at 3929.5,-655.67 h60
  text "SVN REV:" at 4476,-655.67 h60
  text ".VersionControl_RevNumber" at 4982,-655.67 h60
  text "TID #:" at 2248,-859 h60
  text ".TID" at 2793.5,-859 h60
  text "PLOT NAME =" at -228.5,-1064.34 h60
  text ".plot_File_Name" at 577,-1064.34 h60
  text "GENERATED    :" at 2250,-1064.34 h60
  text ".Print_Date" at 3119.5,-1064.34 h60
  text ".Print_Time" at 3848.5,-1064.34 h60
  text "TEXAS INSTRUMENTS" at 5113,-1064.34 h60
M6 Assembly Bottom:
  lines w10: -292.5,-727.33 6309.5,-727.33 ; -290.5,-930.67 6309.5,-930.67 ; 1115.5,-1140.5 1115.5,-937.67 ; 1737.5,-727.33 1737.5,-524 ; 2577.5,-727.33 2577.5,-524 ; 3844.5,-1134 3844.5,-524 ; 4733.5,-1134 6309,-1134 6309,-524 -292.5,-524 -292.5,-1134 2304.5,-1134 6309.5,-1134 6309.5,-524
  text "COMPONENTS MARKED 'DNP' SHOULD NOT BE POPULATED." at 6102,-318 h60
  text ".VariantName" at 5058,-434 h60
  text "ASSEMBLY VARIANT:" at 6097,-434 h60
  text ".VersionControl_RevNumber" at 1035.5,-656.17 h60
  text "SVN REV:" at 1541.5,-656.17 h60
  text ".PCB_Rev" at 2088,-656.17 h60
  text "REV:" at 2379.5,-656.17 h60
  text ".PRJ_Number" at 3224,-656.17 h60
  text "BOARD #:" at 3769.5,-656.17 h60
  text "PCB VIEWED FROM BOTTOM SIDE" at 6246,-656.17 h60
  text ".TID" at 3224,-859.5 h60
  text "TID #:" at 3769.5,-859.5 h60
  text "TEXAS INSTRUMENTS" at 904.5,-1064.84 h60
  text ".Print_Time" at 2169,-1064.84 h60
  text ".Print_Date" at 2898,-1064.84 h60
  text "GENERATED    :" at 3767.5,-1064.84 h60
  text ".plot_File_Name" at 5440.5,-1064.84 h60
  text "PLOT NAME =" at 6246,-1064.84 h60
M9 Title Sheet:
  drawing of 57 lines, arcs and shapes, not listed
  text "1" at 739.84,8036.5 h70
  text "2" at 3235.5,8036.5 h70
  text "3" at 5724.84,8036.5 h70
  text "4" at 8231.51,8036.5 h70
  text "5" at 10730.5,8036.5 h70
  text "6" at 13235.5,8036.5 h70
  text "A" at -416.5,6893.5 h70
  text "A" at 14383.5,6893.5 h70
  text "B" at -416.5,4513.5 h70
  text "B" at 14383.5,4513.5 h70
  text "C" at -416.5,2138.5 h70
  text "C" at 14383.5,2138.5 h70
  text "PROJECT TITLE:" at 11343.5,277.5 h45
  text ".PRJ_Title" at 11393.5,144.17 h70
  text "DESIGNED FOR:" at 11343.5,-23.5 h45
  text ".PRJ_Customer" at 11393.5,-163.5 h70
  text "D" at -416.5,-231.5 h70
  text "D" at 14383.5,-231.5 h70
  text "FILE NAME:" at 11343.5,-323.5 h45
  text ".PCB_File_Name_No_Path" at 11393.5,-443.5 h70
  text "Texas Instruments (TI) and/or its licensors do not warrant the accuracy or completeness of this specification" at 6374,-605.34 h45
  text "ENGINEER:" at 11343.5,-613.5 h45
  text "LAYOUT BY:" at 12848.5,-613.5 h45
  text "or any information contained therein. TI and/or its licensors do not warrant that this design will meet" at 6329.01,-718 h45
  text ".PRJ_Engineer" at 11393.5,-768.49 h70
  text ".PCB_Layout" at 12899,-768.49 h70
  text "the specifications, will be suitable for your application or fit for any particular purpose, or will operate in" at 6329.01,-830.67 h45
  text ".Layer_Name" at 577,-858.49 h60
  text "ALTIUM DESIGNER VERSION:" at 12848.5,-923.5 h45
  text "an implementation. TI and/or its licensors do not warrant that the design is production worthy. You should" at 6329.01,-943.33 h45
  text "completely validate and test your design implementation to confirm the system functionality for your application." at 6374,-1056 h45
  text ".print_Scale" at 11393.5,-1056.83 h70
  text ".Application_BuildNumber" at 12899,-1056.83 h70
  text "1" at 739.84,-1263.5 h70
  text "2" at 3235.5,-1263.5 h70
  text "3" at 5724.84,-1263.5 h70
  text "4" at 8231.51,-1263.5 h70
  text "5" at 10730.5,-1263.5 h70
  text "6" at 13235.5,-1263.5 h70
M10 Fab Notes:
  drawing of 173 lines, arcs and shapes, not listed
  text "DESIGN INFORMATION" at 12378.02,6201 h60
  text "MIN. TRACK WIDTH:" at 11733.46,6021 h60
  text "8" at 12829.7,6021 h60
  text "MIL" at 12984.46,6021 h60
  text "MIN. CLEARANCE:" at 11733.46,5889 h60
  text "0.15" at 12769.7,5889 h60
  text "mm" at 13004.19,5889.2 h60
  text "MIN. VIA PAD SIZE:" at 11733.46,5757 h60
  text "20" at 12799.71,5757 h60
  text "MIL" at 12984.46,5757 h60
  text "0.05mm (2MIL)" at 12428.46,5615.29 h60
  text "MINIMUM ANNULAR RING" at 11404.23,5611 h60
  text "EXTERNAL" at 13136.46,5611 h60
  text "PER" at 11604.23,5493 h60
  text "IPC-D-275 CLASS 2 LEVEL C" at 11824.23,5493 h60
  text "MIL, HOLES" at 13312.46,5380.71 h60
  text "+/-" at 12920,5380 h60
  text "+/-" at 13774,5380 h60
  text "REGISTRATION TOLERANCES:" at 11404.23,5375 h60
  text "METAL" at 12604,5375 h60
  text "5" at 13180.2,5375 h60
  text "3" at 14013.2,5375 h60
  text "MIL" at 14129.46,5375 h60
  text "+/-" at 13774,5262 h60
  text "HOLE SIZE TOLERANCE (UNLESS OTHERWISE SPECIFIED):" at 11404.23,5257 h60
  text "3" at 14013.2,5257 h60
  text "MIL" at 14129.46,5257 h60
  text "MATERIAL:" at 11329.46,5047.54 h60
  text "FR-4 High Tg" at 12315.9,4907.21 h60
  text "FR-408" at 11750.46,4898.64 h60
  text "OTHER" at 13238.46,4898.64 h60
  text "X" at 12161,4895 h60
  text "62 MIL (1.6mm) +/-10%" at 12070.56,4735.92 h60
  text "THICKNESS:" at 11404.23,4731.64 h60
  text "X" at 11942.4,4731.64 h60
  text "OTHER" at 13355.46,4731.64 h60
  text "TOLERANCE:" at 11404.23,4573.64 h60
  text "X" at 12243.53,4573.64 h60
  text "ANSI IPC-6012 TYPE 3 CLASS 2" at 12430.48,4573.64 h60
  text "OTHER +/-" at 12430.46,4417.64 h60
  text "BOW & TWIST:" at 11404.23,4260.64 h60
  text "X" at 12243.53,4260.64 h60
  text "ANSI IPC-6012 TYPE 3 CLASS 2" at 12430.48,4260.64 h60
  text "OTHER +/-" at 12430.46,4102.13 h60
  text "DRILLING:" at 11329.46,3963.64 h60
  text "REFERENCE:" at 11404.23,3846.64 h60
  text "X" at 12052.46,3846.64 h60
  text "AS SHOWN" at 12239.46,3846.64 h60
  text "X" at 12953.46,3846.64 h60
  text "NC_DRILL FILES" at 13090.46,3846.64 h60
  text "PTH COPPER THICKNESS:" at 11404.23,3688.64 h60
  text "X" at 12534.46,3688.64 h60
  text "20-30 um" at 12671.46,3688.64 h60
  text "OTHER" at 13388.46,3688.64 h60
  text "BOARD FINISH:" at 11329.46,3529.64 h60
  text "SILKSCREEN:" at 11484.68,3411.64 h60
  text "X" at 12433.46,3411.64 h60
  text "TOP" at 12559.46,3411.64 h60
  text "X" at 12943.46,3411.64 h60
  text "BOTTOM" at 13070.46,3411.64 h60
  text "SILKSCREEN COLOR:" at 11484.68,3244.64 h60
  text "X" at 12432.42,3244.64 h60
  text "WHITE" at 12559.46,3244.64 h60
  text "OTHER" at 13070.46,3244.64 h60
  text "X" at 12563.42,3085.44 h60
  text "GREEN" at 12690.46,3085.44 h60
  text "OTHER" at 13308.46,3085.44 h60
  text "SOLDER RESIST COLOR:" at 11484.68,3074.64 h60
  text "X" at 12563.42,2915.44 h60
  text "MATTE" at 12690.46,2915.44 h60
  text "SEMI-GLOSS" at 13308,2914.8 h60
  text "IMMERSION GOLD (ENIG)" at 12390.46,2726.92 h60
  text "ENEPIG" at 13728,2723.64 h60
  text "SURFACE FINISH:" at 11329.46,2722.64 h60
  text "X" at 12203.51,2722.64 h60
  text "IMM. TIN/SILVER OR EQUIV" at 11659,2565.64 h60
  text "OTHER" at 13090.46,2565.64 h60
  text "ARRAY/PANEL:" at 11329.46,2386.64 h60
  text "CUT AND TRIM PER M1 BOARD OUTLINE" at 12390.46,2382.35 h60
  text "N.C. ROUTE" at 12390.46,2230.64 h60
  text "X" at 13069.46,2230.64 h60
  text "V. SCORE" at 13256.46,2230.64 h60
  text "CERTIFICATION:" at 11329.46,2093.64 h60
  text "MATERIALS AND WORKMANSHIP FOR ALL PCBS" at 12054.46,2093.64 h60
  text "TO MEET OR EXCEED THE REQUIREMENTS OF:" at 12054.46,1995.64 h60
  text "X" at 11680.96,1859.13 h60
  text "ANSI IPC-A-600F CLASS ->" at 11819.96,1859.13 h60
  text "X" at 13459.02,1859.13 h60
  text "2" at 13577.96,1859.14 h60
  text "1" at 13262.96,1857.64 h60
  text "3" at 13931.96,1857.64 h60
  text "X" at 12495.02,1699.64 h60
  text "RoHS" at 12631.96,1699.64 h60
  text "OTHER" at 13276.36,1699.64 h60
  text "PER ORDER" at 13673.42,1699.64 h60
  text "ALL BOARDS MUST MEET OR EXCEED UL94-V0 REQUIREMENTS." at 11357,1534 h60
  text "PCB MUST BEAR THE UL94V-0 UL REGISTERED MATERIAL ID NUMBER" at 11357,1414 h60
  text "ADDITIONAL REQUIREMENTS:" at 11329.46,1240.64 h60
  text "MICROSECTION:" at 11404.23,1125.64 h60
  text "YES" at 12309.96,1125.64 h60
  text "REQUIRED" at 13171.46,969.49 h60
  text "BARE BOARD ELEC. TEST:" at 11404.23,966.64 h60
  text "NONE" at 12709.96,966.64 h60
  text "X" at 13044.46,966.64 h60
  text "PER ORDER" at 13763.46,966.64 h60
  text ".Layer_Name" at 577,-858.49 h60
M11 Gerber Information:
  lines w10: -292,-930.17 6308,-930.17 ; -292,-726.83 6310,-726.83 ; -292,-523.5 -292,-1133.5 3713,-1133.5 6310,-1133.5 6310,-523.5 -291.5,-523.5 -291.5,-1133.5 1284,-1133.5 ; 2173,-1133.5 2173,-523.5 ; 3440,-726.83 3440,-523.5 ; 4280,-726.83 4280,-523.5 ; 4902,-1140 4902,-937.17
  text "ALL ARTWORK VIEWED FROM TOP SIDE" at -228.5,-655.67 h60
  text "BOARD #:" at 2248,-655.67 h60
  text ".PRJ_Number" at 2793.5,-655.67 h60
  text "REV:" at 3638,-655.67 h60
  text ".PCB_Rev" at 3929.5,-655.67 h60
  text "SVN REV:" at 4476,-655.67 h60
  text ".VersionControl_RevNumber" at 4982,-655.67 h60
  text "LAYER NAME =" at -228.5,-858.49 h60
  text "TID #:" at 2248,-859 h60
  text ".TID" at 2793.5,-859 h60
  text "PLOT NAME =" at -228.5,-1064.34 h60
  text ".plot_File_Name" at 577,-1064.34 h60
  text "GENERATED    :" at 2250,-1064.34 h60
  text ".Print_Date" at 3119.5,-1064.34 h60
  text ".Print_Time" at 3848.5,-1064.34 h60
  text "TEXAS INSTRUMENTS" at 5113,-1064.34 h60
M12 Stackup:
  drawing of 191 lines, arcs and shapes, not listed
  text "Layer" at 9790.34,7830 h60
  text "Name" at 10200.26,7830 h60
  text "Material" at 11130,7830 h60
  text "Thickness" at 11989.77,7830 h60
  text "Constant" at 12639.6,7830 h60
  text "Board Layer Stack" at 13209.46,7830 h60
  text "1" at 9790.34,7710 h60
  text "Top Overlay" at 10200.26,7710 h60
  text "2" at 9790.34,7590 h60
  text "Top Solder" at 10200.26,7590 h60
  text "Solder Resist" at 11130,7590 h60
  text "0.40mil" at 11989.77,7590 h60
  text "3.5" at 12639.6,7590 h60
  text "3" at 9790.34,7470 h60
  text "Top Layer" at 10200.26,7470 h60
  text "Copper" at 11130,7470 h60
  text "1.40mil" at 11989.77,7470 h60
  text "4" at 9790.34,7350 h60
  text "Dielectric1" at 10200.26,7350 h60
  text "FR-4" at 11130,7350 h60
  text "59.20mil" at 11989.77,7350 h60
  text "4.8" at 12639.6,7350 h60
  text "5" at 9790.34,7230 h60
  text "Bottom Layer" at 10200.26,7230 h60
  text "Copper" at 11130,7230 h60
  text "1.40mil" at 11989.77,7230 h60
  text "6" at 9790.34,7110 h60
  text "Bottom Solder" at 10200.26,7110 h60
  text "Solder Resist" at 11130,7110 h60
  text "0.40mil" at 11989.77,7110 h60
  text "3.5" at 12639.6,7110 h60
  text "7" at 9790.34,6990 h60
  text "Bottom Overlay" at 10200.26,6990 h60
  text ".Layer_Name" at 577,-858.49 h60
M13 Component Bodies Top:
  text ".Layer_Name" at 577,-858.49 h60
M14 Component Bodies Bottom:
  text ".Layer_Name" at 577,-858.49 h60
M15 Courtyards Top:
  text ".Layer_Name" at 577,-858.49 h60
M16 Courtyards Bottom:
  text ".Layer_Name" at 577,-858.49 h60
Drill Drawing:
  circle w10: c5348.9,3302.78 r13.28
  circle w10: c5348.9,3302.78 r22.14
  circle w10: c5348.9,2804.67 r22.14
  lines w10: 5326.76,2384.04 5371.04,2384.04 5371.04,2428.32 5326.76,2428.32 5326.76,2384.04 ; 5326.76,2494.73 5337.83,2494.73 5348.9,2483.66 5359.97,2494.73 5371.04,2494.73 5359.97,2505.8 5371.04,2516.87 5359.97,2516.87 5348.9,2527.94 5337.83,2516.87 5326.76,2516.87 5337.83,2505.8 5326.76,2494.73 ; 5326.76,2583.29 5348.9,2594.35 5371.04,2583.29 5359.97,2605.42 5371.04,2627.56 5348.9,2616.49 5326.76,2627.56 5337.83,2605.42 5326.76,2583.29 ; 5326.76,2727.18 5371.04,2727.18 5348.9,2682.91 5326.76,2727.18 ; 5326.76,2882.15 5326.76,2893.22 5337.83,2904.29 5326.76,2915.36 5326.76,2926.43 5337.83,2926.43 5348.9,2915.36 5359.97,2926.43 5371.04,2926.43 5371.04,2915.36 5359.97,2904.29 5371.04,2893.22 5371.04,2882.15 5359.97,2882.15 5348.9,2893.22 5337.83,2882.15 5326.76,2882.15 ; 5326.76,2981.77 5348.9,2992.84 5371.04,2981.77 5359.97,3003.91 5371.04,3026.05 5348.9,3014.98 5326.76,3026.05 5337.83,3003.91 5326.76,2981.77 ; 5326.76,3081.4 5371.04,3081.4 5371.04,3125.67 5326.76,3125.67 5326.76,3081.4 ; 5326.76,3203.16 5348.9,3181.02 5371.04,3203.16 5348.9,3225.3 5326.76,3203.16 ; 5335.62,2499.16 5342.26,2499.16 5348.9,2492.52 5355.54,2499.16 5362.18,2499.16 5355.54,2505.8 5362.18,2512.44 5355.54,2512.44 5348.9,2519.08 5342.26,2512.44 5335.62,2512.44 5342.26,2505.8 5335.62,2499.16 ; 5335.62,2592.14 5348.9,2598.78 5362.18,2592.14 5355.54,2605.42 5362.18,2618.71 5348.9,2612.06 5335.62,2618.71 5342.26,2605.42 5335.62,2592.14 ; 5335.62,2718.33 5362.18,2718.33 5348.9,2691.76 5335.62,2718.33 ; 5335.62,3090.25 5362.18,3090.25 5362.18,3116.82 5335.62,3116.82 5335.62,3090.25
  lines w12: 5286,2354.15 8398.94,2354.15 ; 5286,3350.38 8398.94,3350.38 ; 5601.63,2254.53 5601.63,3450 ; 5918.82,2254.53 5918.82,3450 ; 6540.56,2254.53 6540.56,3450 ; 6784.88,2254.53 6784.88,3450 ; 7145.22,2254.53 7145.22,3450 ; 7854.73,2254.53 7854.73,3450 ; 5286,2254.53 8398.94,2254.53 8398.94,3450 5286,3450 5286,2254.53
  text "Symbol" at 5345.77,3380.26 h72
  text "Quantity" at 5631.52,3380.26 h72
  text "Finished Hole Size" at 5948.7,3380.26 h72
  text "Plated" at 6570.45,3380.26 h72
  text "Hole Type" at 6814.77,3380.26 h72
  text "Drill Layer Pair" at 7175.11,3380.26 h72
  text "Hole Tolerance" at 7884.62,3380.26 h72
  text "2" at 5631.52,3280.64 h60
  text "7.87mil (0.200mm)" at 5948.7,3280.64 h60
  text "PTH" at 6570.45,3280.64 h60
  text "Round" at 6814.77,3280.64 h60
  text "Top Layer - Bottom Layer" at 7175.11,3280.64 h60
  text "422" at 5631.52,3181.02 h60
  text "8.00mil (0.203mm)" at 5948.7,3181.02 h60
  text "PTH" at 6570.45,3181.02 h60
  text "Round" at 6814.77,3181.02 h60
  text "Top Layer - Bottom Layer" at 7175.11,3181.02 h60
  text "3" at 5631.52,3081.4 h60
  text "10.00mil (0.254mm)" at 5948.7,3081.4 h60
  text "PTH" at 6570.45,3081.4 h60
  text "Round" at 6814.77,3081.4 h60
  text "Top Layer - Bottom Layer" at 7175.11,3081.4 h60
  text "9" at 5631.52,2981.77 h60
  text "16.00mil (0.406mm)" at 5948.7,2981.77 h60
  text "PTH" at 6570.45,2981.77 h60
  text "Round" at 6814.77,2981.77 h60
  text "Top Layer - Bottom Layer" at 7175.11,2981.77 h60
  text "8" at 5631.52,2882.15 h60
  text "39.37mil (1.000mm)" at 5948.7,2882.15 h60
  text "PTH" at 6570.45,2882.15 h60
  text "Round" at 6814.77,2882.15 h60
  text "Top Layer - Bottom Layer" at 7175.11,2882.15 h60
  text "15" at 5631.52,2782.53 h60
  text "39.37mil (1.000mm)" at 5948.7,2782.53 h60
  text "PTH" at 6570.45,2782.53 h60
  text "Round" at 6814.77,2782.53 h60
  text "Top Layer - Bottom Layer" at 7175.11,2782.53 h60
  text "+/-7.87mil" at 7884.62,2782.53 h60
  text "3" at 5631.52,2682.91 h60
  text "40.00mil (1.016mm)" at 5948.7,2682.91 h60
  text "PTH" at 6570.45,2682.91 h60
  text "Round" at 6814.77,2682.91 h60
  text "Top Layer - Bottom Layer" at 7175.11,2682.91 h60
  text "3" at 5631.52,2583.29 h60
  text "40.16mil (1.020mm)" at 5948.7,2583.29 h60
  text "PTH" at 6570.45,2583.29 h60
  text "Round" at 6814.77,2583.29 h60
  text "Top Layer - Bottom Layer" at 7175.11,2583.29 h60
  text "40" at 5631.52,2483.66 h60
  text "45.28mil (1.150mm)" at 5948.7,2483.66 h60
  text "PTH" at 6570.45,2483.66 h60
  text "Round" at 6814.77,2483.66 h60
  text "Top Layer - Bottom Layer" at 7175.11,2483.66 h60
  text "2" at 5631.52,2384.04 h60
  text "125.98mil (3.200mm)" at 5948.7,2384.04 h60
  text "PTH" at 6570.45,2384.04 h60
  text "Round" at 6814.77,2384.04 h60
  text "Top Layer - Bottom Layer" at 7175.11,2384.04 h60
  text "+/-11.81mil" at 7884.62,2384.04 h60
  text "507 Total" at 5631.52,2284.42 h60
  text ".Layer_Name" at 577,-858.49 h60
Mechanical 17:
  text ".Layer_Name" at 577,-858.49 h60
Mechanical 18:
  text ".Layer_Name" at 577,-858.49 h60
Mechanical 19:
  text ".Layer_Name" at 577,-858.49 h60

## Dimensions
0,2049 to 3153,2050 on M2 Board Dimensions
0,0 to -2,2050 on M2 Board Dimensions
0,-400 to 1000,-400 on M2 Board Dimensions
